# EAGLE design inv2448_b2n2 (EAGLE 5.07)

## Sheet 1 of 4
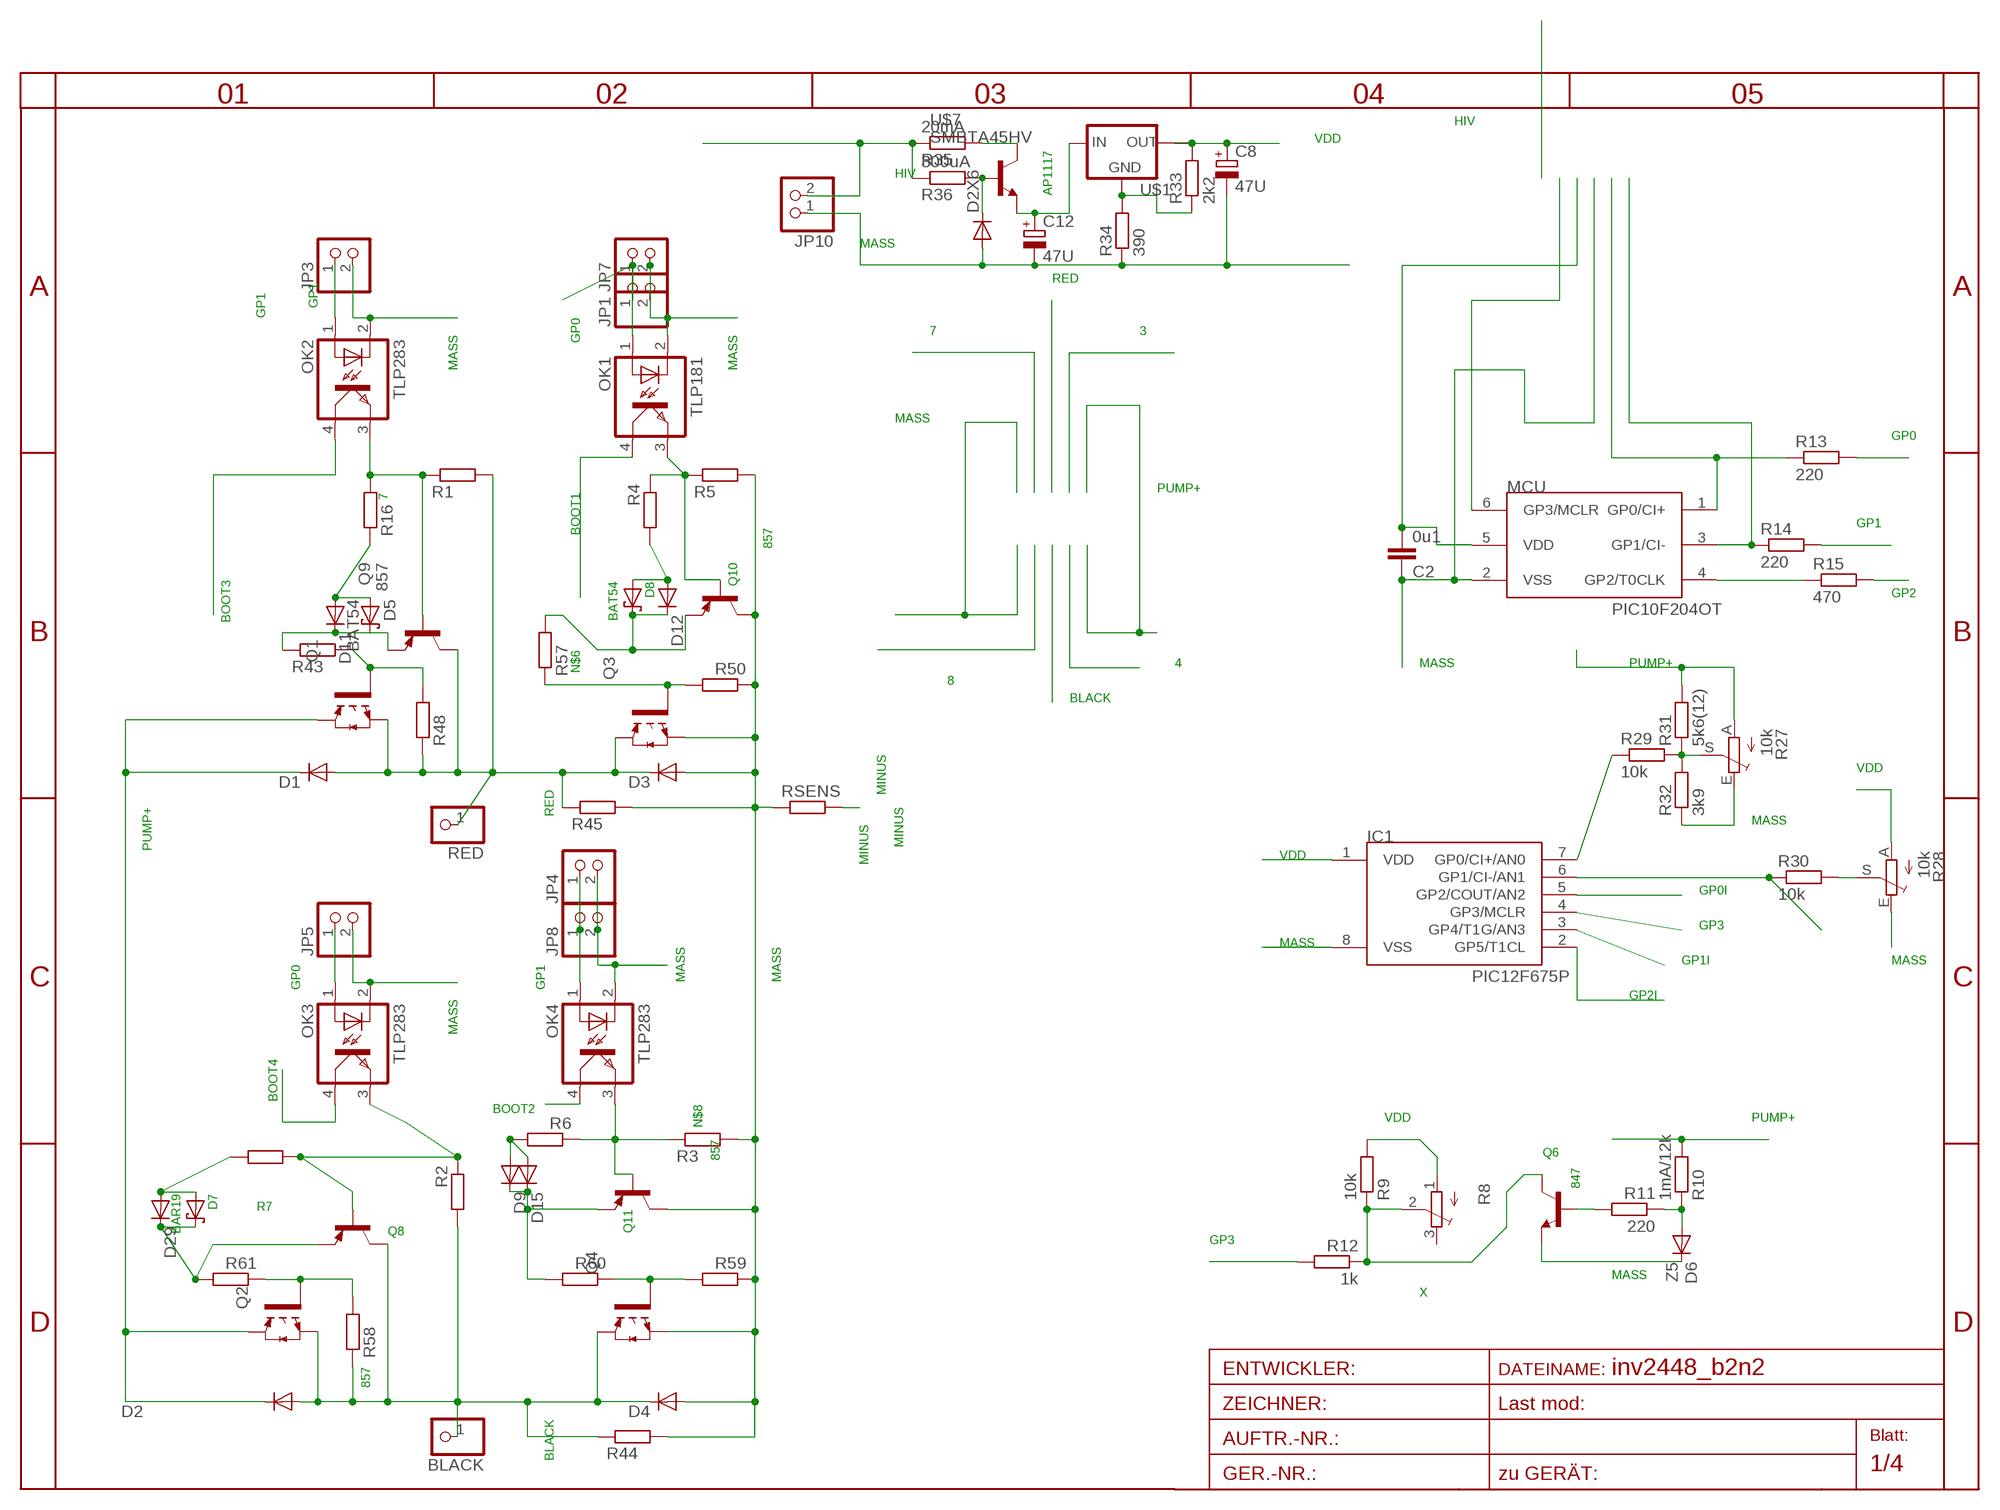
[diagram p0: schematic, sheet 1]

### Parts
BLACK  PINHD-1X14.5MM  [1X4MM5]
C2  0u1  C-EUC0805  [C0805]
C8  47U  CPOL-EUE  [PANASONIC_E]
C12  47U  CPOL-EUSMCA  [SMC_A]
D1  DIODE-SMC  [SMC]
D2  DIODE-SMC  [SMC]
D2X6  DIODE-MINIMELF  [MINIMELF]
D3  DIODE-SMC  [SMC]
D4  DIODE-SMC  [SMC]
D5  BAT54  [SOT23]
D6  Z5  DIODE-MINIMELF  [MINIMELF]
D7  BAR19  BAT54  [SOT23]
D8  BAT54  [SOT23]
D9  DIODE-MINIMELF  [MINIMELF]
D11  DIODE-MINIMELF  [MINIMELF]
D12  DIODE-MINIMELF  [MINIMELF]
D15  DIODE-MINIMELF  [MINIMELF]
D29  DIODE-MINIMELF  [MINIMELF]
IC1  PIC12F675P  [DIL8]
JP1  PINHD-1X2STR  [1X02]
JP3  PINHD-1X2STR  [1X02]
JP4  PINHD-1X2STR  [1X02]
JP5  PINHD-1X2STR  [1X02]
JP7  PINHD-1X2STR  [1X02]
JP8  PINHD-1X2STR  [1X02]
JP10  PINHD-1X2STR  [1X02]
MCU  PIC10F204OT  [SOT23-6]
OK1  TLP181  TLP283FLAT  [FLAT-4]
OK2  TLP283  TLP283FLAT  [FLAT-4]
OK3  TLP283  TLP283FLAT  [FLAT-4]
OK4  TLP283  TLP283FLAT  [FLAT-4]
Q1  IRG4BC15UD-S  [D2PACK]
Q2  IRG4BC15UD-S  [D2PACK]
Q3  IRG4BC15UD-S  [D2PACK]
Q4  IRG4BC15UD-S  [D2PACK]
Q6  847  BC847ALT1SMD  [SOT23]
Q8  857  BC857ALT1SMD  [SOT23-BEC]
Q9  857  BC857ALT1SMD  [SOT23-BEC]
Q10  857  BC857ALT1SMD  [SOT23-BEC]
Q11  857  BC857ALT1SMD  [SOT23-BEC]
R1  R-EU_R1206  [R1206]
R2  R-EU_R1206  [R1206]
R3  R-EU_R1206  [R1206]
R4  R-EU_R0805  [R0805]
R5  R-EU_R1206  [R1206]
R6  R-EU_R1206  [R1206]
R7  R-EU_R0805  [R0805]
R8  TRIM_EU-3223W  [3223W]
R9  10k  R-EU_R1206  [R1206]
R10  1mA/12k  R-EU_R1206  [R1206]
R11  220  R-EU_R1206  [R1206]
R12  1k  R-EU_0204/7  [0204/7]
R13  220  R-EU_R1206  [R1206]
R14  220  R-EU_0207/10  [0207/10]
R15  470  R-EU_0207/20  [0207/20]
R16  R-EU_R0805  [R0805]
R27  10k  TRIM_EU-RAND160  [RANDL]
R28  10k  TRIM_EU-RAND160  [RANDL]
R29  10k  R-EU_0207/30  [0207/30]
R30  10k  R-EU_R0805  [R0805]
R31  5k6(12)  R-EU_0207/30  [0207/30]
R32  3k9  R-EU_R0805  [R0805]
R33  2k2  R-EU_R0805  [R0805]
R34  390  R-EU_R0805  [R0805]
R35  20mA  R-EU_R1206  [R1206]
R36  300uA  R-EU_R1206  [R1206]
R43  R-EU_0204/2V  [0204V]
R44  R-EU_0204/2V  [0204V]
R45  R-EU_0204/2V  [0204V]
R48  R-EU_R1206  [R1206]
R50  R-EU_R1206  [R1206]
R57  R-EU_0204/2V  [0204V]
R58  R-EU_R1206  [R1206]
R59  R-EU_R1206  [R1206]
R60  R-EU_0204/2V  [0204V]
R61  R-EU_0204/2V  [0204V]
RED  PINHD-1X14.5MM  [1X4MM5]
RSENS  R-EU_CERAM55  [CERAM55]
U$1  AP1117  [SOT223]
U$7  SMBTA45HV  [SOT23HV]

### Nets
3: OK1.3(EMIT) Q10.B R4.1 R5.1
4: OK3.3(EMIT) Q8.B R2.1 R7.2
7: OK2.3(EMIT) Q9.B R1.1 R16.2
BLACK: BLACK.1 D2.A D4.C Q2.3(E) Q4.2(C) Q8.C R2.2 R44.1 R58.1 ; also sheet 2
BOOT1: OK1.4(COL) ; also sheet 2
BOOT2: OK4.4(COL) ; also sheet 2
BOOT3: OK2.4(COL) ; also sheet 2
BOOT4: OK3.4(COL) ; also sheet 2
GP0: JP1.1 JP5.1 JP7.1 OK1.1(A) OK3.1(A) R13.2
GP0I: IC1.5(GP2/COUT/AN2) MCU.1(GP0/CI+) R13.1
GP1: JP3.1 JP4.1 JP8.1 OK2.1(A) OK4.1(A) R14.2
GP1I: IC1.3(GP4/T1G/AN3) MCU.3(GP1/CI-) R14.1
GP2: R15.2 ; also sheet 2
GP2I: IC1.2(GP5/T1CL) MCU.4(GP2/T0CLK) R15.1
GP3: IC1.4(GP3/MCLR) MCU.6(GP3/MCLR) R12.2
HIV: JP10.2 R35.1 R36.1 ; also sheet 2
MASS: C2.1 C8.- C12.- D2X6.A D3.A D4.A D6.C IC1.8(VSS) JP1.2 JP3.2 JP4.2 JP5.2 JP7.2 JP8.2 JP10.1 MCU.2(VSS) OK1.2(C) OK2.2(C) OK3.2(C) OK4.2(C) Q3.3(E) Q4.3(E) Q6.2(E) Q10.C Q11.C R3.2 R5.2 R27.E R28.E R32.1 R34.1 R44.2 R45.2 R50.1 R59.1 RSENS.1 ; also sheet 2,4
MINUS: RSENS.2 ; also sheet 2,3,4
N$2: D8.1(A) D12.A R4.2
N$4: D6.A R10.1 R11.1
N$5: Q6.1(B) R11.2
N$6: D8.3(C) D12.C Q10.E R57.2
N$7: D9.C D15.C Q11.E R60.2
N$8: OK4.3(EMIT) Q11.B R3.1 R6.1
N$9: D9.A D15.A R6.2
N$10: D7.3(C) D29.C Q8.E R61.2
N$11: D7.1(A) D29.A R7.1
N$12: D5.1(A) D11.A R16.1
N$14: Q1.1(G) R43.2 R48.2
N$24: R28.S R30.2
N$30: R33.1 R34.2 U$1.1(GND)
N$31: IC1.6(GP1/CI-/AN1) R30.1
N$32: D2X6.C R36.2 U$7.1(B)
N$33: R35.2 U$7.3(C)
N$34: R27.S R29.2 R31.1 R32.2
N$35: IC1.7(GP0/CI+/AN0) R29.1
N$36: C12.+ U$1.3(IN) U$7.2(E)
N$37: Q2.1(G) R58.2 R61.1
N$55: Q3.1(G) R50.2 R57.1
N$56: Q4.1(G) R59.2 R60.1
N$57: D5.3(C) D11.C Q9.E R43.1
PUMP+: D1.C D2.C Q1.2(C) Q2.2(C) R10.2 R27.A R31.2 ; also sheet 2,3
RED: D1.A D3.C Q1.3(E) Q3.2(C) Q9.C R1.2 R45.1 R48.1 RED.1 ; also sheet 2
VDD: C2.2 C8.+ IC1.1(VDD) MCU.5(VDD) R8.1(A) R9.2 R28.A R33.2 U$1.2(OUT) U$1.4(TAB)
X: Q6.3(C) R8.2(S) R9.1 R12.1
Unconnected: R8.3(E)

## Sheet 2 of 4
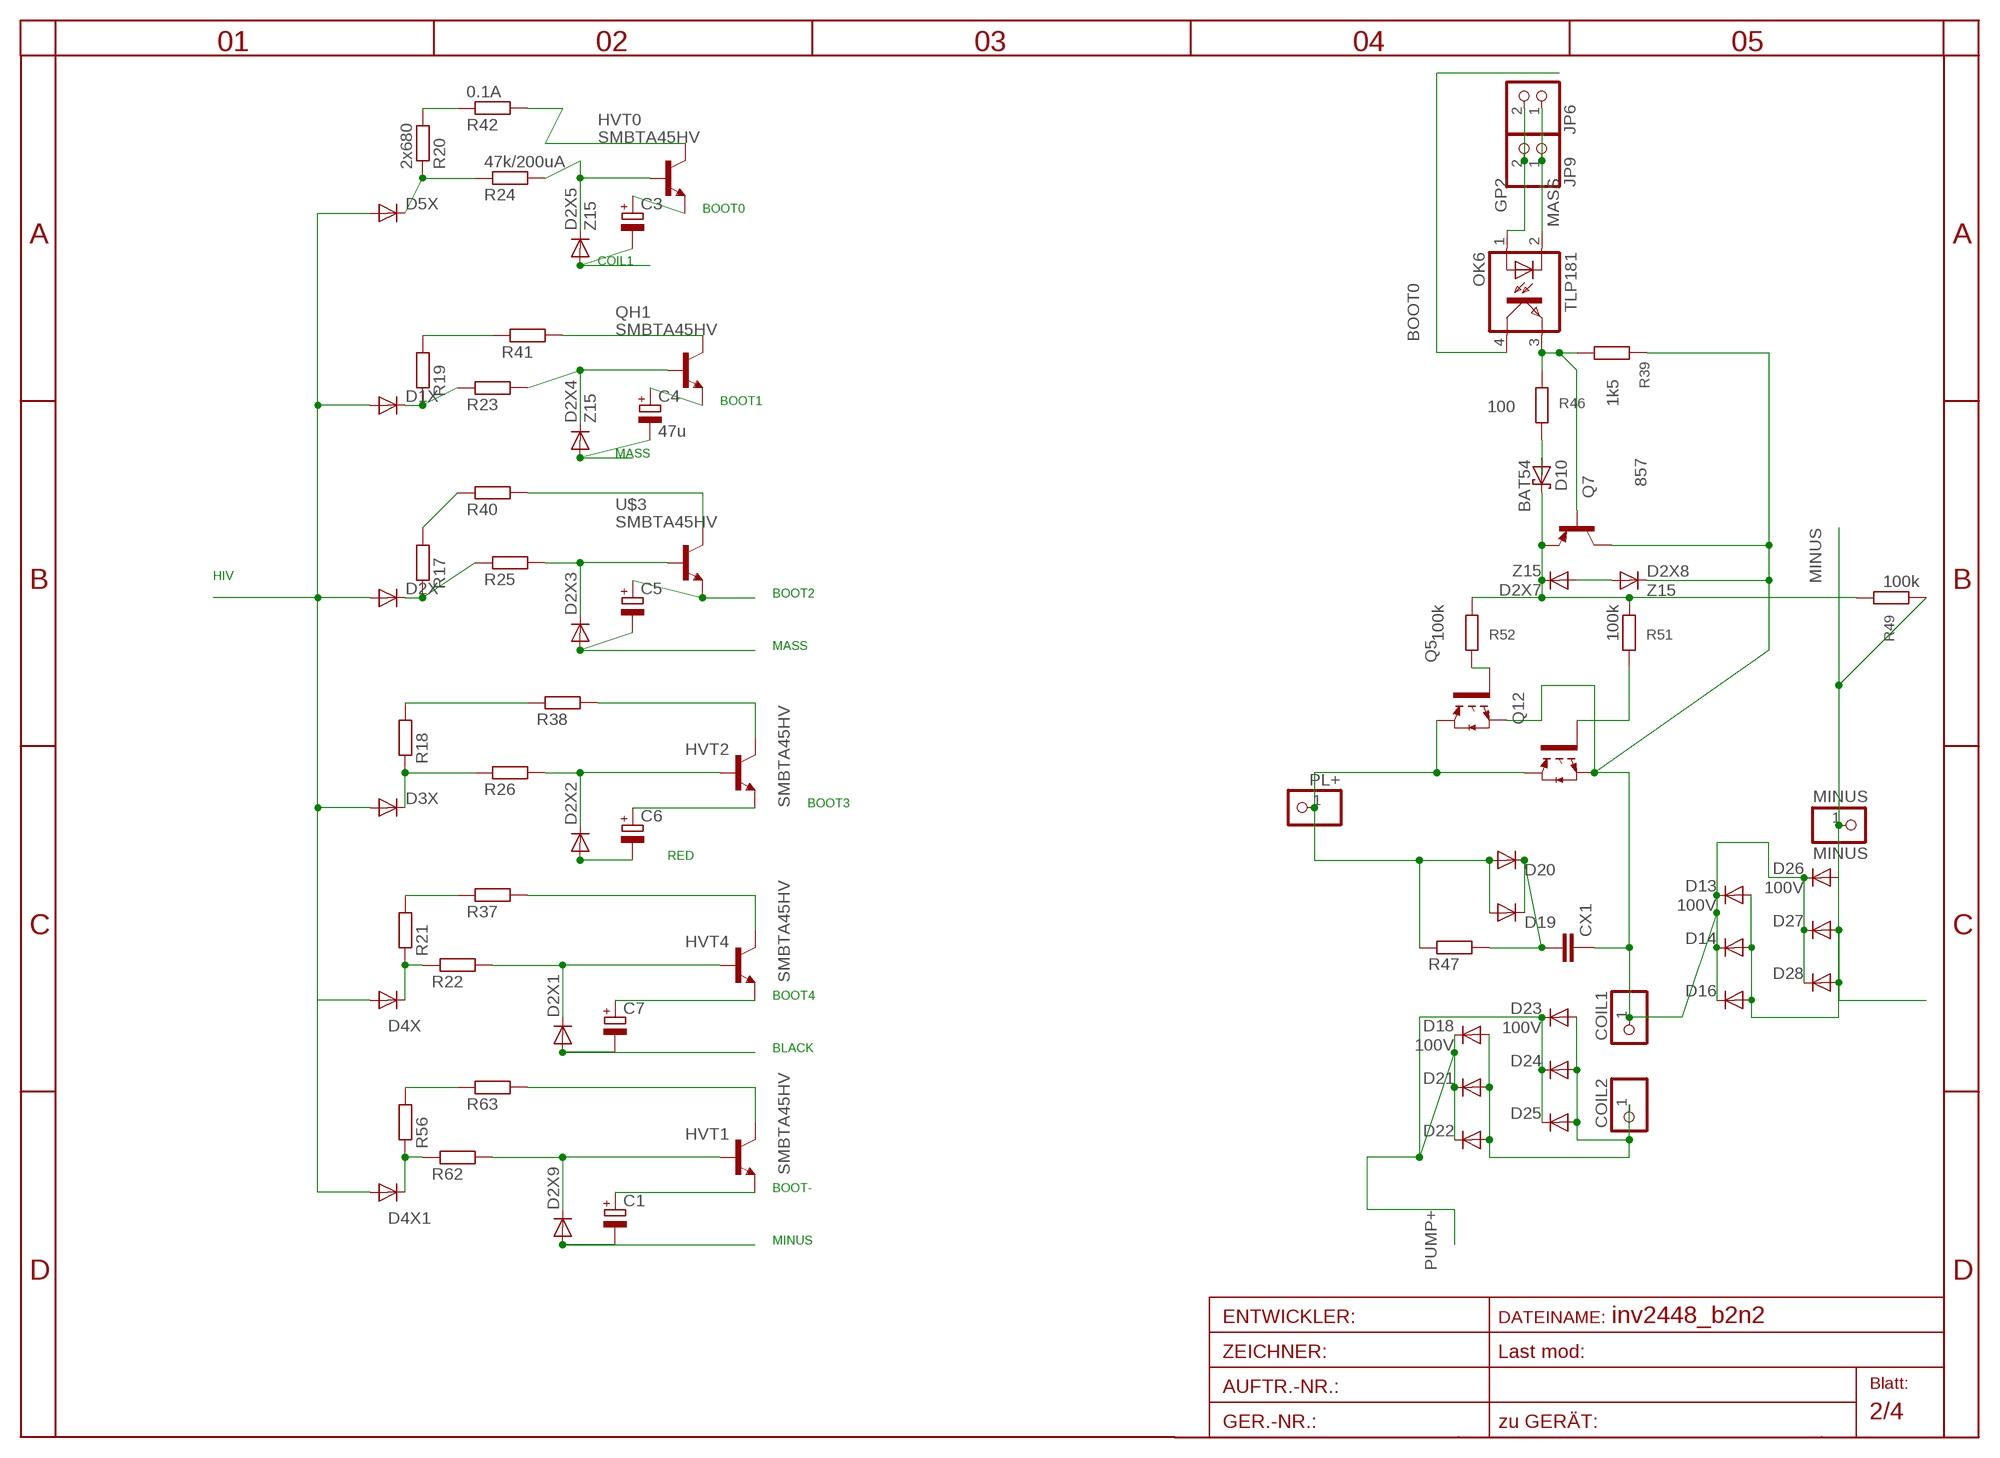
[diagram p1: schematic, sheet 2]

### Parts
C1  CPOL-EUE  [PANASONIC_E]
C3  CPOL-EUE  [PANASONIC_E]
C4  47u  CPOL-EUE  [PANASONIC_E]
C5  CPOL-EUE  [PANASONIC_E]
C6  CPOL-EUE  [PANASONIC_E]
C7  CPOL-EUE  [PANASONIC_E]
COIL1  PINHD-1X14.5MM  [1X4MM5]
COIL2  PINHD-1X14.5MM  [1X4MM5]
CX1  CXXC22B10  [XC22B10]
D1X  DIODE-SMA-DO214  [SMA-DO214AC]
D2X  DIODE-SMA-DO214  [SMA-DO214AC]
D2X1  DIODE-MINIMELF  [MINIMELF]
D2X2  DIODE-MINIMELF  [MINIMELF]
D2X3  DIODE-MINIMELF  [MINIMELF]
D2X4  Z15  DIODE-MINIMELF  [MINIMELF]
D2X5  Z15  DIODE-MINIMELF  [MINIMELF]
D2X7  Z15  DIODE-MINIMELF  [MINIMELF]
D2X8  Z15  DIODE-MINIMELF  [MINIMELF]
D2X9  DIODE-MINIMELF  [MINIMELF]
D3X  DIODE-SMA-DO214  [SMA-DO214AC]
D4X  DIODE-SMA-DO214  [SMA-DO214AC]
D4X1  DIODE-SMA-DO214  [SMA-DO214AC]
D5X  DIODE-SMA-DO214  [SMA-DO214AC]
D10  BAT54  [SOT23]
D13  100V  DIODE-SMC  [SMC]
D14  DIODE-SMC  [SMC]
D16  DIODE-SMC  [SMC]
D18  100V  DIODE-SMC  [SMC]
D19  DIODE-SMC  [SMC]
D20  DIODE-SMC  [SMC]
D21  DIODE-SMC  [SMC]
D22  DIODE-SMC  [SMC]
D23  100V  DIODE-SMC  [SMC]
D24  DIODE-SMC  [SMC]
D25  DIODE-SMC  [SMC]
D26  100V  DIODE-SMC  [SMC]
D27  DIODE-SMC  [SMC]
D28  DIODE-SMC  [SMC]
HVT0  SMBTA45HV  [SOT23HV]
HVT1  SMBTA45HV  [SOT23HV]
HVT2  SMBTA45HV  [SOT23HV]
HVT4  SMBTA45HV  [SOT23HV]
JP6  PINHD-1X2STR  [1X02]
JP9  PINHD-1X2STR  [1X02]
MINUS  MINUS  PINHD-1X14.5MM  [1X4MM5]
OK6  TLP181  TLP283FLAT  [FLAT-4]
PL+  PINHD-1X14.5MM  [1X4MM5]
Q5  IRG4BC15UD-S  [D2PACK]
Q7  857  BC857ALT1SMD  [SOT23-BEC]
Q12  IRG4BC15UD-S  [D2PACK]
QH1  SMBTA45HV  [SOT23HV]
R17  R-EU_R1206  [R1206]
R18  R-EU_R1206  [R1206]
R19  R-EU_R1206  [R1206]
R20  2x680  R-EU_R1206  [R1206]
R21  R-EU_R1206  [R1206]
R22  R-EU_R1206  [R1206]
R23  R-EU_R1206  [R1206]
R24  47k/200uA  R-EU_R1206  [R1206]
R25  R-EU_R1206  [R1206]
R26  R-EU_R1206  [R1206]
R37  R-EU_R1206  [R1206]
R38  R-EU_R1206  [R1206]
R39  1k5  R-EU_R1206  [R1206]
R40  R-EU_R1206  [R1206]
R41  R-EU_R1206  [R1206]
R42  0.1A  R-EU_R1206  [R1206]
R46  100  R-EU_R1206  [R1206]
R47  R-EU_0207/5V  [0207/5V]
R49  100k  R-EU_0207/30  [0207/30]
R51  100k  R-EU_0204/2V  [0204V]
R52  100k  R-EU_0204/2V  [0204V]
R56  R-EU_R1206  [R1206]
R62  R-EU_R1206  [R1206]
R63  R-EU_R1206  [R1206]
U$3  SMBTA45HV  [SOT23HV]

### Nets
BLACK: C7.- D2X1.A ; also sheet 1
BOOT0: C3.+ HVT0.2(E) OK6.4(COL)
BOOT1: C4.+ QH1.2(E) ; also sheet 1
BOOT2: C5.+ U$3.2(E) ; also sheet 1
BOOT3: C6.+ HVT2.2(E) ; also sheet 1
BOOT4: C7.+ HVT4.2(E) ; also sheet 1
BOOT-: C1.+ HVT1.2(E) ; also sheet 4
COIL1: C3.- COIL1.1 CX1.1 D2X5.A D2X8.C D13.C D14.C D16.C D26.C D27.C D28.C Q5.3(E) Q7.C Q12.3(E) R39.1
COIL2: COIL2.1 D18.A D21.A D22.A D23.A D24.A D25.A ; also sheet 4
GP2: JP6.2 JP9.2 OK6.1(A) ; also sheet 1
HIV: D1X.A D2X.A D3X.A D4X1.A D4X.A D5X.A D19.A D20.A PL+.1 Q5.2(C) Q12.2(C) R47.1 ; also sheet 1
MASS: C4.- C5.- D2X3.A D2X4.A JP6.1 JP9.1 OK6.2(C) ; also sheet 1,4
MINUS: C1.- D2X9.A D13.A D14.A D16.A D26.A D27.A D28.A MINUS.1 R49.1 ; also sheet 1,3,4
N$1: D2X7.C D10.3(C) Q7.E R49.2 R51.1 R52.1
N$3: D10.1(A) R46.1
N$13: D3X.K(C) R18.1 R26.1
N$15: D4X.K(C) R21.1 R22.1
N$16: D2X.K(C) R17.1 R25.1
N$17: D1X.K(C) R19.1 R23.1
N$18: D5X.K(C) R20.1 R24.1
N$19: D2X1.C HVT4.1(B) R22.2
N$20: D2X5.C HVT0.1(B) R24.2
N$21: D2X4.C QH1.1(B) R23.2
N$22: D2X2.C HVT2.1(B) R26.2
N$23: D2X3.C R25.2 U$3.1(B)
N$25: HVT2.3(C) R38.2
N$26: HVT4.3(C) R37.2
N$27: R40.2 U$3.3(C)
N$28: HVT0.3(C) R42.2
N$29: QH1.3(C) R41.2
N$38: R21.2 R37.1
N$39: R18.2 R38.1
N$40: R17.2 R40.1
N$41: R19.2 R41.1
N$42: R20.2 R42.1
N$43: OK6.3(EMIT) Q7.B R39.2 R46.2
N$44: D2X7.A D2X8.A
N$47: Q5.1(G) R52.2
N$48: Q12.1(G) R51.2
N$58: D4X1.K(C) R56.1 R62.1
N$59: D2X9.C HVT1.1(B) R62.2
N$60: HVT1.3(C) R63.2
N$61: R56.2 R63.1
PUMP+: D18.C D21.C D22.C D23.C D24.C D25.C ; also sheet 1,3
RED: C6.- D2X2.A ; also sheet 1
SNUB: CX1.2 D19.C D20.C R47.2

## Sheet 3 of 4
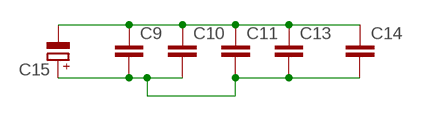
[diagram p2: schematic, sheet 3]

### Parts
C9  C-EUC1206  [C1206]
C10  C-EUC1206  [C1206]
C11  C-EUC1206  [C1206]
C13  C-EUC1206  [C1206]
C14  C-EUC1206  [C1206]
C15  CPOL-EUE2.5-7  [E2,5-7]

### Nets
MINUS: C9.1 C10.1 C11.1 C13.1 C14.1 C15.- ; also sheet 1,2,4
PUMP+: C9.2 C10.2 C11.2 C13.2 C14.2 C15.+ ; also sheet 1,2

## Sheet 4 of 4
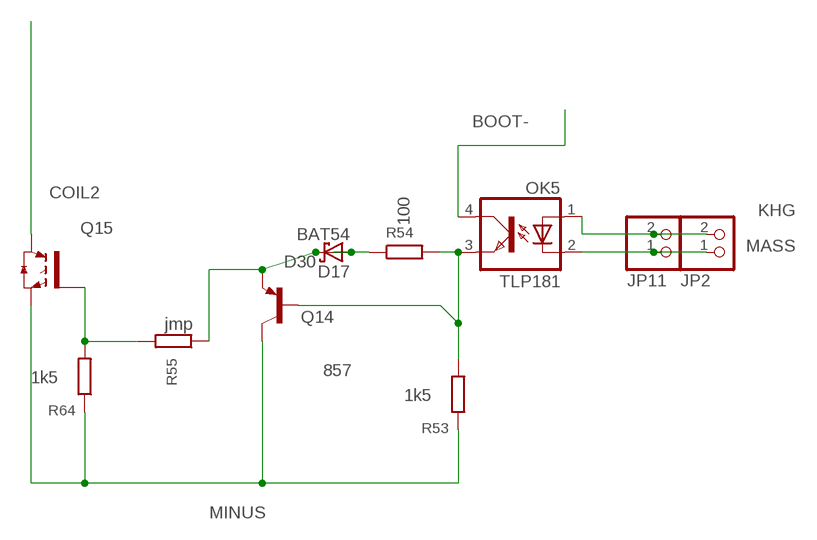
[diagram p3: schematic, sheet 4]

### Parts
D17  BAT54  [SOT23]
D30  DIODE-MINIMELF  [MINIMELF]
JP2  PINHD-1X2STR  [1X02]
JP11  PINHD-1X2STR  [1X02]
OK5  TLP181  TLP283FLAT  [FLAT-4]
Q14  857  BC857ALT1SMD  [SOT23-BEC]
Q15  IRG4BC15UD-S  [D2PACK]
R53  1k5  R-EU_R1206  [R1206]
R54  100  R-EU_R0805  [R0805]
R55  jmp  R-EU_0204/2V  [0204V]
R64  1k5  R-EU_R1206  [R1206]

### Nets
BOOT-: OK5.4(COL) ; also sheet 2
COIL2: Q15.2(C) ; also sheet 2
KHG: JP2.2 JP11.2 OK5.1(A)
MASS: JP2.1 JP11.1 OK5.2(C) ; also sheet 1,2
MINUS: Q14.C Q15.3(E) R53.1 R64.1 ; also sheet 1,2,3
N$46: OK5.3(EMIT) Q14.B R53.2 R54.2
N$49: D17.3(C) D30.C Q14.E R55.1
N$50: D17.1(A) D30.A R54.1
N$53: Q15.1(G) R55.2 R64.2

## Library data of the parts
BLACK COIL1 COIL2 MINUS PL+ RED = pinhead:PINHD-1X1: PIN HEADER
C1 C3-C7 C15 = rcl:CPOL-EU: POLARIZED CAPACITOR, European symbol
C2 C9-C11 C13 C14 = rcl:C-EU: CAPACITOR, European symbol
C8 C12 = rcl-2:CPOL-EU: POLARIZED CAPACITOR, European symbol
CX1 = rcl:CX: X CAPACITOR
D1 D1X D2 D2X D2X1-D2X9 D3 D3X D4 D4X D4X1 D5X D6 D9 D11-D16 D18-D30 = diode:DIODE-: DIODE
D5 D7 D8 D10 D17 = diode:BAT54: Schottky Diodes
HVT0 HVT1 HVT2 HVT4 QH1 U$3 U$7 = transistor-npn:SMBTA45
IC1 = microchip-5:PIC12F6*: uPC nW 1k Program Flash memory 2x Timer Comparator 10b A/D converter/ 4xIN
JP1-JP11 = pinhead:PINHD-1X2: PIN HEADER
MCU = microchip-3:PIC10F2*: uPC nW 0,25/0,5k Program Flash memory Comparator
OK1-OK6 = optocoupler:TLP283: TOSHIBA PHOTOCOUPLER GaAs IRED & PHOTO-TRANSISTOR Source: http://www.semicon.toshiba.co.jp/td/en/Opto/Photocoupler/en_20050928_TLP283_datasheet.pdf
Q1-Q5 Q12 Q15 = transistor-power:IRG4BC15UD-: INSULATED GATE BIPOLAR TRANSISTOR WITH ULTRAFAST SOFT RECOVERY DIODE
Q6 = transistor-npn:BC847*: NPN Transistor
Q7-Q11 Q14 = transistor-pnp:BC857*: PNP Transistror
R1-R7 R9-R12 R16-R26 R35-R38 R40-R45 R47 R48 R50 R56-R63 RSENS = rcl:R-EU_: RESISTOR, European symbol
R8 R27 R28 = pot:TRIM_EU-: POTENTIOMETER
R13-R15 R29-R34 R39 R46 R49 R51-R55 R64 = rcl-2:R-EU_: RESISTOR, European symbol
U$1 = v-reg:AP1117

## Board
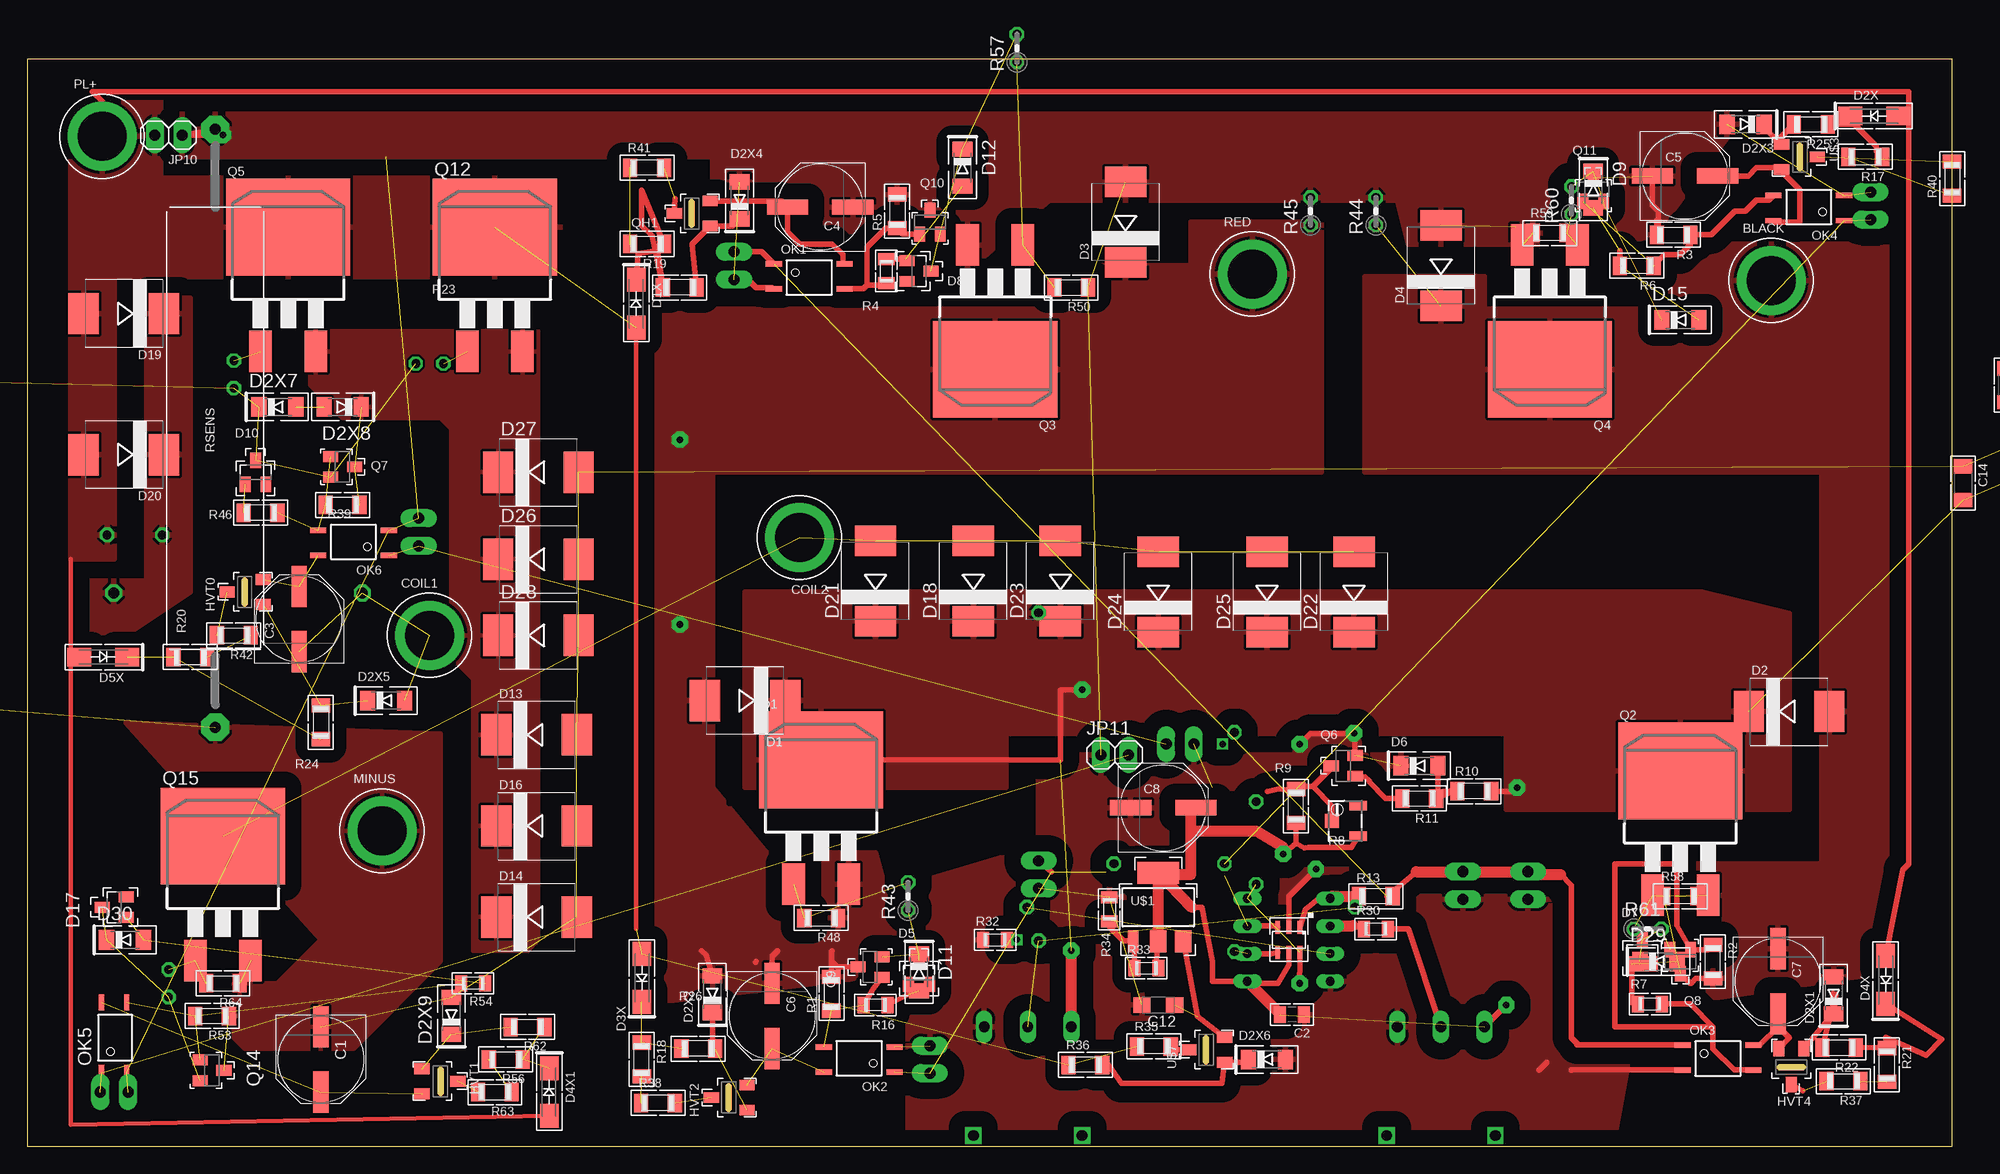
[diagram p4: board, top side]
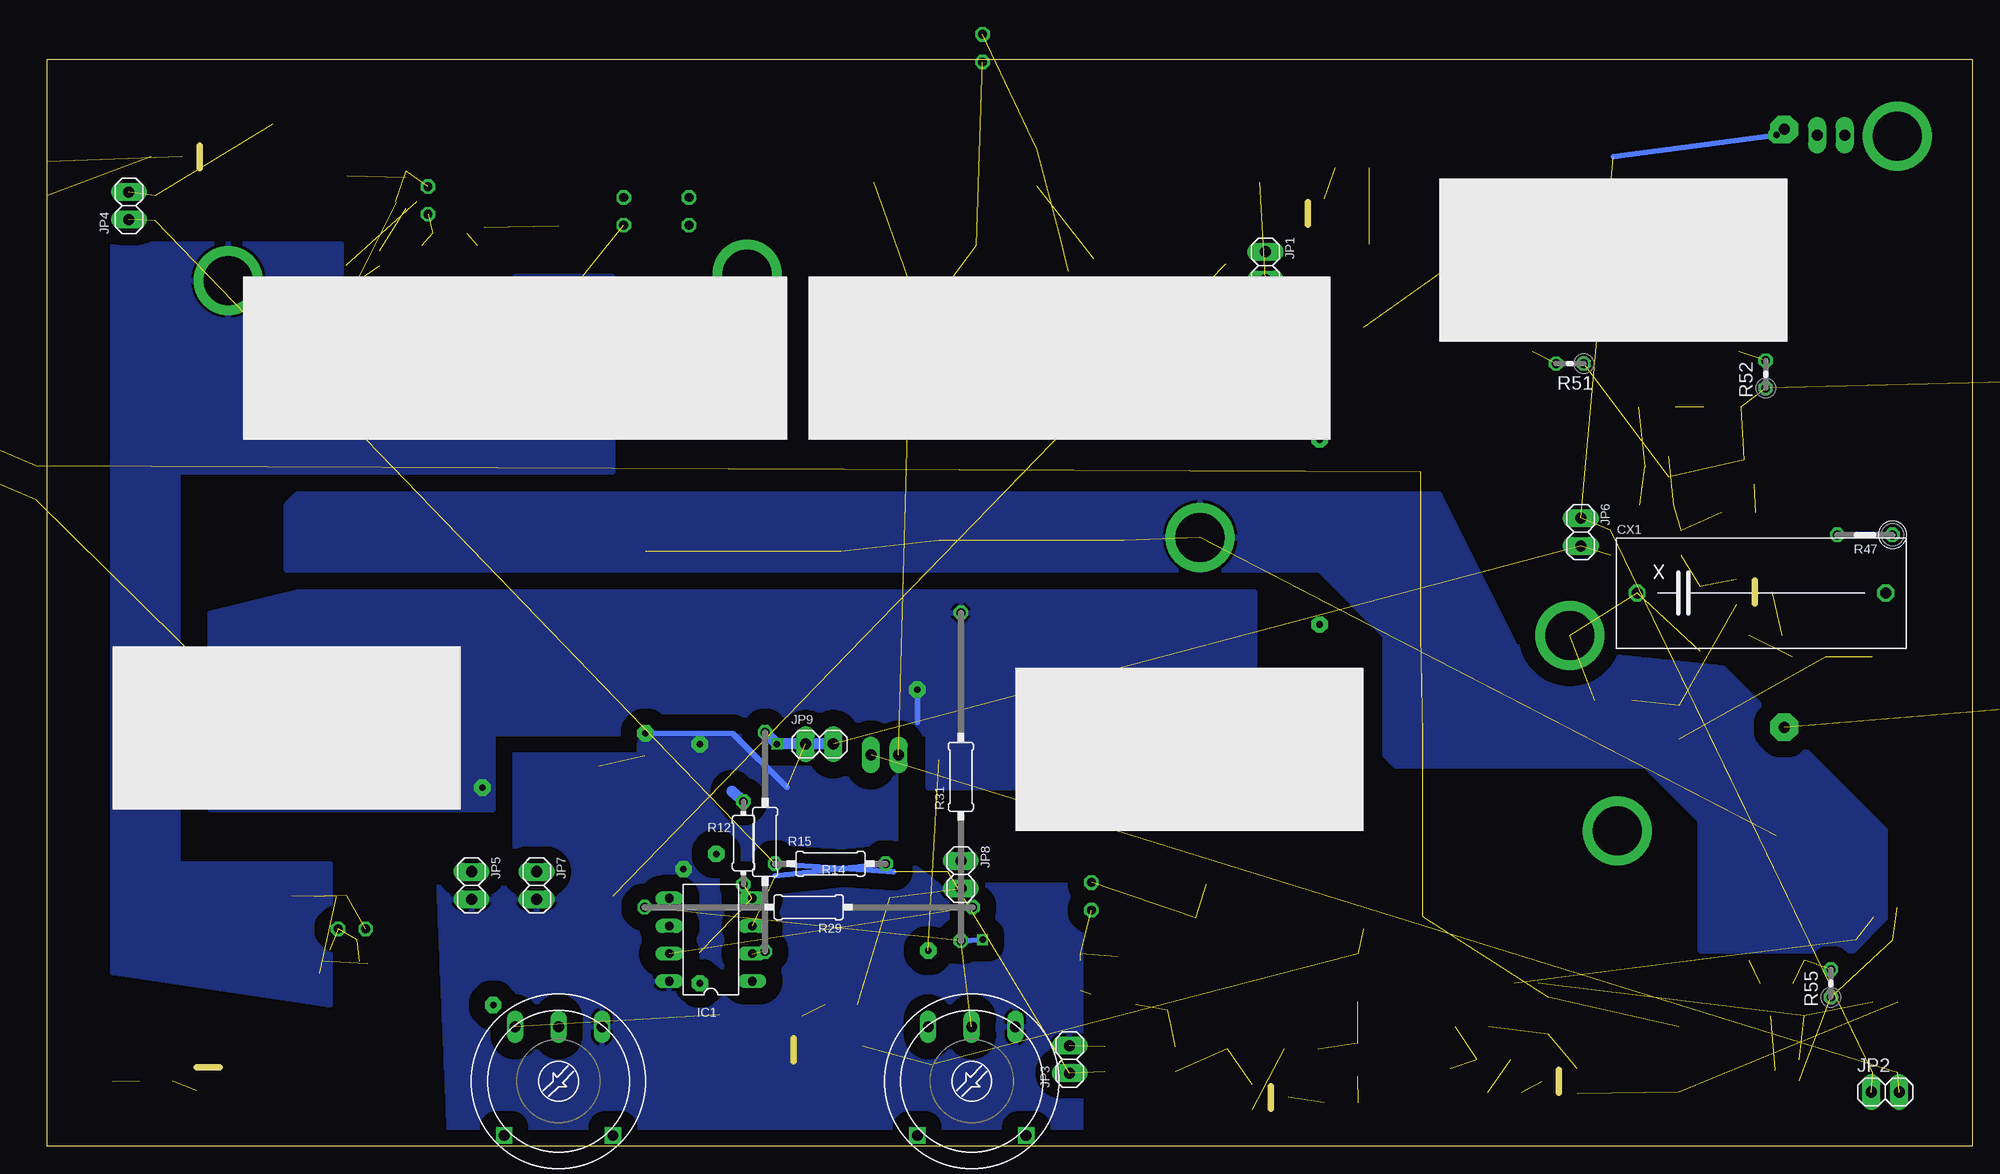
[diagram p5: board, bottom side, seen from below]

Size 177 x 100 mm. Coordinates in mm from the lower left corner, seen from the top.
Outline: 0,0 177,0 177,100 0,100 0,0
Copper layers (1*16): Top 0.035mm / dielectric 1.5mm / Bottom 0.035mm
Design rules "default *": minimum track width 10mil, minimum drill 20mil, track to track 8mil, track to pad 8mil, pad to pad 8mil, via to via 8mil, smd to smd 8mil, copper to edge 40mil, drill to drill 8mil, minimum pad ring 10mil, minimum via ring 8mil, stop-mask expansion 4mil, vias tented up to drill 0mil, thermal gap 10mil

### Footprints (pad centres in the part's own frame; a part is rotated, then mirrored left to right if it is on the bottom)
1X4MM5 = drill 4.5 pad 6.35 round: 1 0,0
PANASONIC_E = smd 3.8 x 1.4: + 3,0; - -3,0
C0805 = smd 1.1 x 1.5: 1 -1.1,0; 2 1.1,0
C1206 = smd 1.3 x 1.7: 1 -1.55,0; 2 1.55,0
SMC_A = smd 1.6 x 1.4: + -1.5,0; - 1.5,0
E2,5-7 = drill 0.813 pad 1.6 round: + -1.27,0 | drill 0.813 pad 1.6 octagon: - 1.27,0
XC22B10 = drill 1.016 octagon: 1 -11.43,0.025; 2 11.43,0.025
SMC = smd 2.8 x 3.8: A 3.7,0; C -3.7,0
SMA-DO214AC = smd 2.2 x 1.7: A 2.2,0; K -2.2,0
MINIMELF = smd 1.4 x 1.8: A 1.7,0; C -1.7,0
SOT23 = smd 1 x 1.4: 1 -0.95,-1.1; 2 0.95,-1.1; 3 0,1.1
SOT23HV = smd 1 x 1.4: 1 -1.15,-1.7; 2 1.15,-1.7; 3 0,1.6
DIL8 = drill 0.8 long: 1 -3.81,-3.81; 2 -1.27,-3.81; 3 1.27,-3.81; 4 3.81,-3.81; 5 3.81,3.81; 6 1.27,3.81; 7 -1.27,3.81; 8 -3.81,3.81
1X02 = drill 1.016 pad 1.676 long: 1 -1.27,0; 2 1.27,0
SOT23-6 = smd 0.45 x 1.2: 1 -1.016,-1.15; 2 0,-1.15; 3 1.016,-1.15; 4 1.016,1.15; 5 0,1.15; 6 -1.016,1.15
FLAT-4 = smd 1.5 x 0.5: 1 -3.25,1.15; 2 -3.25,-1.15; 3 3.25,-1.15; 4 3.25,1.15
D2PACK = smd 2.083 x 3.81: 1 -2.54,-8.89; 3 2.54,-8.89 | smd 11.43 x 8.89: 2 0,2.54
SOT23-BEC = smd 1 x 1.4: B -0.95,-1.1; C 0,1.1; E 0.95,-1.1
R1206 = smd 1.3 x 1.7: 1 -1.55,0; 2 1.55,0
R0805 = smd 1.1 x 1.5: 1 -1.1,0; 2 1.1,0
3223W = smd 0.9 x 1.6: 1 -1.4,-1.215; 3 1.4,-1.215 | smd 1.3 x 1.3: 2 0,1.215
0204/7 = drill 0.813 octagon: 1 -3.81,0; 2 3.81,0
0207/10 = drill 0.813 octagon: 1 -5.08,0; 2 5.08,0
0207/20 = drill 0.813 octagon: 1 -10.08,0; 2 10.08,0
RANDL = drill 1 long: A -4,5; E 4,5; S 0,5 | drill 1 square: P$1 -5,-5; P$2 5,-5
0207/30 = drill 0.813 octagon: 1 -15.08,0; 2 15.08,0
0204V = drill 0.813 octagon: 1 -1.27,0; 2 1.27,0
0207/5V = drill 0.813 octagon: 1 -2.54,0; 2 2.54,0
0204V' = drill 0.8 pad 1.27 octagon: 1 -1.27,0; 2 1.27,0
CERAM55 = drill 1 pad 2.54 octagon: 1 -27.5,0; 2 27.5,0
SOT223 = smd 1 x 2: 1 -2.3,-3.15 | smd 1.5 x 2: 2 0,-3.15; 3 2.3,-3.15 | smd 3.8 x 2: 4 0,3.15

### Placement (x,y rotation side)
BLACK  160.35,79.64 0 top
C1  27,8 270 top
C2  116.3,12.12 180 top
C3  25,48.5 90 top
C4  72.92,86.38 180 top
C5  152.43,89.25 0 top
C6  68.5,12 270 top
C7  160.98,15.19 270 top
C8  104.46,31.15 0 top
C9  not placed on the board
C10  not placed on the board
C11  not placed on the board
C12  104,13 180 top
C13  not placed on the board
C14  178,61 270 top
C15  not placed on the board
COIL1  37,47 0 top
COIL2  71,56 180 top
CX1  19.39,50.87 0 bottom
D1  66,41 180 top
D1X  56,77.5 270 top
D2  162,40 0 top
D2X  169.83,94.78 0 top
D2X1  166.1,13.9 90 top
D2X2  63,14 90 top
D2X3  158,94 180 top
D2X4  65.5,87 90 top
D2X5  33,41 0 top
D2X6  114,8 0 top
D2X7  23,68 0 top
D2X8  29,68 180 top
D2X9  39,12 90 top
D3  101,85 90 top
D3X  56.5,15.5 90 top
D4  130,81 90 top
D4X  170.88,15.31 90 top
D4X1  48,5 270 top
D5  82,16 0 top
D5X  7,45 180 top
D6  128,35 0 top
D7  148.5,17.9 0 top
D8  82,80.5 270 top
D9  144,88 270 top
D10  21,62 0 top
D11  82,16 270 top
D12  86,90 270 top
D13  46.84,37.85 0 top
D14  46.84,21.09 0 top
D15  152,76 0 top
D16  46.84,29.47 0 top
D17  8,22 90 top
D18  87,52 90 top
D19  8.88,76.59 180 top
D20  8.88,63.62 180 top
D21  78,52 90 top
D22  122,51 90 top
D23  95,52 90 top
D24  104,51 90 top
D25  114,51 90 top
D26  47,54 0 top
D27  47,62 0 top
D28  47,47 0 top
D29  150,17 0 top
D30  9,19 0 top
HVT0  20,51 90 top
HVT1  38,6 270 top
HVT2  64.5,4.5 90 top
HVT4  162.2,7.3 180 top
IC1  116,19 90 bottom
JP1  65,81 270 bottom
JP2  8,5 0 bottom
JP3  83,8 90 bottom
JP4  169.5,86.5 90 bottom
JP5  138,24 270 bottom
JP6  36,56.5 270 bottom
JP7  132,24 270 bottom
JP8  93,25 270 bottom
JP9  106,37 0 bottom
JP10  13,93 180 top
JP11  100,36 0 top
MCU  116,19 180 top
MINUS  32.62,29.02 0 top
OK1  71.9,80 0 top
OK2  76.5,8 180 top
OK3  155.46,8.18 0 top
OK4  163.81,86.29 180 top
OK5  8,10 90 top
OK6  30,55.5 180 top
PL+  6.89,92.9 0 top
Q1  73,33 0 top
Q2  152,32 0 top
Q3  89,74 180 top
Q4  140,74 180 top
Q5  24,82 0 top
Q6  121,35 90 top
Q7  29,62.5 270 top
Q8  152,17 180 top
Q9  77.5,16.5 90 top
Q10  83,85 0 top
Q11  144,88 0 top
Q12  43,82 0 top
Q14  17,7 270 top
Q15  18,26 0 top
QH1  61.1,85.8 90 top
R1  73.95,14.05 90 top
R2  155,17 270 top
R3  151.38,83.83 180 top
R4  79,80.5 90 top
R5  80,86 90 top
R6  148,81 180 top
R7  149.2,13.1 0 top
R8  121.18,29.94 90 top
R9  116.67,31.3 270 top
R10  133.05,32.67 0 top
R11  128,32 180 top
R12  113,27.9 270 bottom
R13  124,23 0 top
R14  105,26 180 bottom
R15  111,28 90 bottom
R16  78,13 180 top
R17  169,91 180 top
R18  56.5,8 270 top
R19  57,83 180 top
R20  15,45 0 top
R21  171,7.5 270 top
R22  166.6,9.1 180 top
R23  60,79 0 top
R24  27,39 90 top
R25  164,94 180 top
R26  61.7,9 0 top
R27  92,6 0 bottom
R28  130,6 0 bottom
R29  107,22 180 bottom
R30  124,20 0 top
R31  93,34 90 bottom
R32  89,19 0 top
R33  102.9,16.4 0 top
R34  99.5,21.8 270 top
R35  103.6,9.2 0 top
R36  97.3,7.5 0 top
R37  167,6 180 top
R38  58,4 0 top
R39  29,59 180 top
R40  177,89 90 top
R41  57,90 0 top
R42  19,47 180 top
R43  81,23 90 top
R44  124,86 90 top
R45  118,86 90 top
R46  21.46,58.28 0 top
R47  9.88,56.24 180 bottom
R48  73,21 180 top
R49  not placed on the board
R50  96,79 180 top
R51  100k  [0204V']  37,72 180 bottom
R52  100k  [0204V']  19,71 90 bottom
R53  17,12 180 top
R54  41,15 180 top
R55  jmp  [0204V']  13,15 90 bottom
R56  44,8 180 top
R57  91,101 90 top
R58  152,23 0 top
R59  140,84 0 top
R60  142,87 90 top
R61  149,20 0 top
R62  46,11 180 top
R63  43,5 180 top
R64  18,15 180 top
RED  112.65,80.23 0 top
RSENS  17.29,66.04 270 top
U$1  104,22 0 top
U$3  163,91 270 top
U$7  108.4,8.9 90 top

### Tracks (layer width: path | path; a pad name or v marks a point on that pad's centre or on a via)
3
  Top 0.5: 77.2,79.2 77.2,82.7 78.95,84.45 R5.1 80.55,83.9 Q10.B | 77.2,79.2 76.9,78.9 75.2,78.9 OK1.3 | 77.2,79.2 78.8,79.2 R4.1
4
  Top 0.5: OK3.3 156.97,7.03 155,9 155,11 | 155,11 146,11 146,26 151.7,26 151.7,20.35 Q8.B 154.55,18.1 R2.1 | R7.2 152.9,13.1 155,11
7  (2 unrouted)
  Top 0.5: Q9.B 77.8,14.55 R16.2
BLACK  (3 unrouted)
  Top 0.5: R2.2 153.45,15.45 153,15 152.9,15 Q8.C
  pour Top (isolate 1.5, rank 2): 123,80 134,80 134,77 150,77 150,83 171,83 171,16 151,13 151,26 165,26 165,62 123,62
  pour Bottom (isolate 1.5, rank 2): 125,80 134,80 134,77 150,77 150,83 171,83 171,16 151,13 151,26 165,26 165,62 125,62
BOOT0  (2 unrouted)
BOOT1
  Top 0.5: OK1.4 75,81.3 75,82 74,83 71,83 69.92,84.08 C4.+ 69.35,86.95 QH1.2
BOOT2
  Top 0.5: C5.+ 158.25,89.25 159,90 161.15,90 U$3.2 161.3,89.7 163,88 163,85 160.7,85 OK4.4
BOOT3  (2 unrouted)
BOOT4
  Top 0.5: OK3.4 159.33,9.33 161,11 | 161,11 161,12.17 C7.+ | HVT4.2 162,10 161,11
BOOT-  (2 unrouted)
COIL1  (5 unrouted)
  pour Top: 26,75 47,75 47,19 46,18 41,18 41,43 39,45 39,66 38,67 29,67 26,70
COIL2  (7 unrouted)
  pour Bottom (isolate 1.5): 155,53 60,53 54,47 54,36 53,35 30,35 25,30 25,18 11,18 8,21 8,29 23,44 42,46 49,60 154,60 155,59
GP0  (1 unrouted)
  Top 0.5: R13.2 125,23 127.73,25.27 | 142.5,9.5 142,10 142,24 141,25 | 142.5,9.5 142.58,9.41 | JP5.1 138.27,25 | OK3.1 142.5,9.33 142.5,9.5 | JP1.1 67.53,82.27 OK1.1
  Top 1: 127.73,25.27 JP7.1 JP5.1 | 138.27,25 141,25
GP0I
  Top 0.5: MCU.1 117.52,21.82 119,23 119.62,23 IC1.5 120,23
  Top 1: 120,23 R13.1
GP1  (5 unrouted)
  Top 0.5: JP8.1 94.19,25.27
  Bottom 0.5: 99.19,25.27 R14.2
GP1I  (1 unrouted)
  Top 0.5: IC1.3 114.6,20.27 MCU.3
  Bottom 0.5: R14.1 110.1,24.9
GP2  (via drill 0.6)  (2 unrouted)
  Bottom 1: JP9.2 v109.92,37 R15.2
GP2I  (1 unrouted)
  Top 0.5: IC1.2 114.36,17.73 MCU.4
  Bottom 0.5: R15.1 111.08,18
GP3  (via drill 0.6 pad 1.5)  (2 unrouted)
  Top 0.5: MCU.6 117.02,16.98 v117,15
  Bottom 0.5: R12.2 113.2,24.2
HIV  (4 unrouted)
  Top 0.406: 4,45 D5X.A | 4,45 4,54 | D4X1.A 4,2 4,45 | 56,20 D1X.A
  Top 0.5: D4X.A 172.44,25.44 173,26 173,95 | 173,95 173,97 6,97 6.89,96.11 PL+.1 | D2X.A 172.65,94.65 173,95
  pour Top (isolate 1.5, rank 2): 4,96 49,96 49,80 8,80 8,54 4,54
KHG  (2 unrouted)
MASS  (via drill 0.6 pad 1.5)  (17 unrouted)
  Top 0.5: Q4.3 136.83,84.52 | MCU.2 116,23 v118.5,25.5 | Q6.2 122.1,37.9 v122,38 118,38 v117,37 | 139,7 139.75,7.75 | v18,93 14.33,93 RSENS.1 | OK3.2 142,7.03 142,7 | JP1.2 66.27,79.73 67,79 68.5,79 OK1.2 | 149.83,85.17 R3.2 150,84 150,86 149.43,86.57 C5.-
  Bottom 0.5: v122,38 114,38 109,33 | v18,93 33,91
  pour Top (isolate 1.5): 14,95 158,95 149,83 127,83 126,87 94,87 87,81 69,81 65,82 65,87 63,87 63,91 14,91
  pour Top (isolate 1.5, rank 3): 93,38 134,38 134,25 138,25 148,12 146,1 81,1 81,24 91,27 93,27
  pour Bottom (isolate 1.5, rank 3): 99,38 134,38 134,25 141,25 140,1 82,1 82,24 95,24 99,27
MINUS  (16 unrouted)
  pour Top (isolate 1.5): 9,39 38,38 38,17 30,9 20,9 19,10 19,15 23,15 27,19
N$1  (5 unrouted)
N$2  (1 unrouted)
  Top 0.5: R4.2 80.75,81.6 D8.1
N$3  (1 unrouted)
N$4
  Top 0.5: R10.1 130.22,32.67 131.28,32.73 | R11.1 131.28,32.73 | D6.A 129.7,32.3 131.28,32.73
N$5
  Top 0.5: R11.2 124.9,32 123.4,33.5 123.4,33.6 123,34 122.15,34 Q6.1
N$6  (3 unrouted)
N$7  (3 unrouted)
  Top 0.5: Q11.E 144.9,86.85
N$8  (1 unrouted)
  Top 0.5: OK4.3 160.12,87 159,87 158,86 157,86 154.83,83.83 R3.1 152.93,82.93 152,82 150.55,82 R6.1
N$9  (2 unrouted)
  Top 0.5: R6.2 146.45,82.4
N$10  (3 unrouted)
N$11  (1 unrouted)
  Top 0.5: D7.1 147.55,13.2 R7.1
N$12  (1 unrouted)
  Top 0.5: R16.1 81.05,14 D5.1
N$13  (2 unrouted)
N$14  (2 unrouted)
N$15
  Top 0.5: D4X.K 176.06,9.86 174.6,8.4 170.9,10.05 R21.1 R22.1
N$16
  Top 0.5: R25.1 167.43,94 | 167.43,94 D2X.K | 167.43,94 168,94 170,92 170,91.55 R17.1
N$17
  Top 0.5: D1X.K 56.17,82.13 57.9,82.4 57.9,82.55 R23.1 57.45,83.75 56.5,84.7 56.5,87.95 R19.1
N$18  (2 unrouted)
N$19
  Top 0.5: R22.2 166.3,14 D2X1.C 166,14.1 166,12 165.35,11.35 HVT4.1
N$20  (2 unrouted)
N$21
  Top 0.5: R23.2 61.15,83 QH1.1 64.85,84.65 D2X4.C
N$22  (1 unrouted)
  Top 0.5: D2X2.C 63,9.55 R26.2
N$23
  Top 0.5: D2X3.C 159.7,93.75 U$3.1 161.3,92.85 R25.2
N$24
  Top 0.5: R28.S 127,20 R30.2
N$25  (1 unrouted)
N$26  (1 unrouted)
  Top 0.5: HVT4.3 163.25,5.1
N$27  (1 unrouted)
N$28  (1 unrouted)
N$29  (1 unrouted)
  Top 0.5: QH1.3 59.55,87.15
N$30
  Top 0.5: R33.1 101.8,18.75 U$1.1 101.65,18.9 100.8,18.9 99.5,20.2 R34.2
N$31
  Top 0.5: 121.88,20.3 R30.1
  Top 1: IC1.6 121.88,20.3
N$32
  Top 0.5: R36.2 99.4,7.5 100.6,5.8 109.85,5.8 U$7.1 112.05,7.75 D2X6.C
N$33
  Top 0.5: U$7.3 105.45,8.9 R35.2
N$34  (via drill 0.6)  (2 unrouted)
  Top 0.5: R32.2 v91,19
  Bottom 0.5: v91,19 R31.1
N$35  (1 unrouted)
N$36  (1 unrouted)
  Top 0.5: U$7.2 107.6,11.95 U$1.3
N$37  (2 unrouted)
N$38  (1 unrouted)
N$39  (1 unrouted)
N$40  (1 unrouted)
N$41  (1 unrouted)
N$42  (1 unrouted)
N$43  (3 unrouted)
N$44  (1 unrouted)
N$46  (3 unrouted)
N$47  (1 unrouted)
N$48  (1 unrouted)
N$49  (3 unrouted)
N$50  (2 unrouted)
N$53  (2 unrouted)
N$55  (2 unrouted)
N$56  (2 unrouted)
N$57  (3 unrouted)
N$58  (2 unrouted)
N$59  (2 unrouted)
N$60  (1 unrouted)
N$61  (1 unrouted)
PUMP+  (via drill 0.6 pad 1.5)  (7 unrouted)
  Top 0.5: R10.2 136.67,32.67 v137,33 | Q1.2 95,35.54 95,42 v97,42
  Top 1: R27.A v96,18
  Bottom 0.5: v97,42 97,39
  pour Top (isolate 1.5): 162,49 162,31 136,31 136,38 90,38 90,33 66,33 66,51 154,51
  pour Bottom (isolate 1.5): 162,49 162,31 136,31 136,38 96,38 96,33 66,33 66,51 154,51
RED  (via drill 0.6 pad 1.5)
  Top 0.5: 66.95,16.95 67,17 | D2X2.A 62.4,17.6 62,18 | C6.- 68.5,17.5 69,18 | R1.2 73.95,17 | 73.95,17 73.95,17.95 74,18 | Q9.C 74.45,16.5 73.95,17
  other vias: 60,65 60,48
  pour Top (isolate 1.5, rank 2): 119,62 119,85 107,85 107,81 98,81 98,77 56,77 56,13 81,16 78,27 68,27 63,33 63,62
SNUB
  pour Top (isolate 1.5, rank 2): 11,78 15,78 15,51 9,47 5,47 5,52 11,52
VDD  (via drill 0.6 pad 1.5)  (1 unrouted)
  Top 0.5: MCU.5 116,16.7 115,15 112.38,15 IC1.1 109,15.19 109,17 108,22 107.06,21.99 | R28.A v136,13 | 116.67,27.87 R9.2 | 116.67,27.87 v115.5,26.9 115.5,27.5 | 116.67,27.87 117.43,27.47 117.8,27.5 121.75,27.5 R8.1 | 115.2,12.18 C2.2 | R33.2 103.8,16.8 U$1.2 | U$1.4 104,25
  Top 1: IC1.1 115.2,12.18 | 115.5,27.5 113,29 107,29 | U$1.2 U$1.4 107.06,21.99 | 104,25 107,25 107,29 | 107,29 107,30.61 C8.+
X  (1 unrouted)
  Top 0.5: R8.2 119.97,31.34 118.2,33.1 | 118.2,33.1 116.92,33.1 R9.1 116.52,32.7 115.1,32.9 114.05,32.65 | Q6.3 119.9,34.8 118.2,33.1
  Bottom 1: R12.1 114.05,32.65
